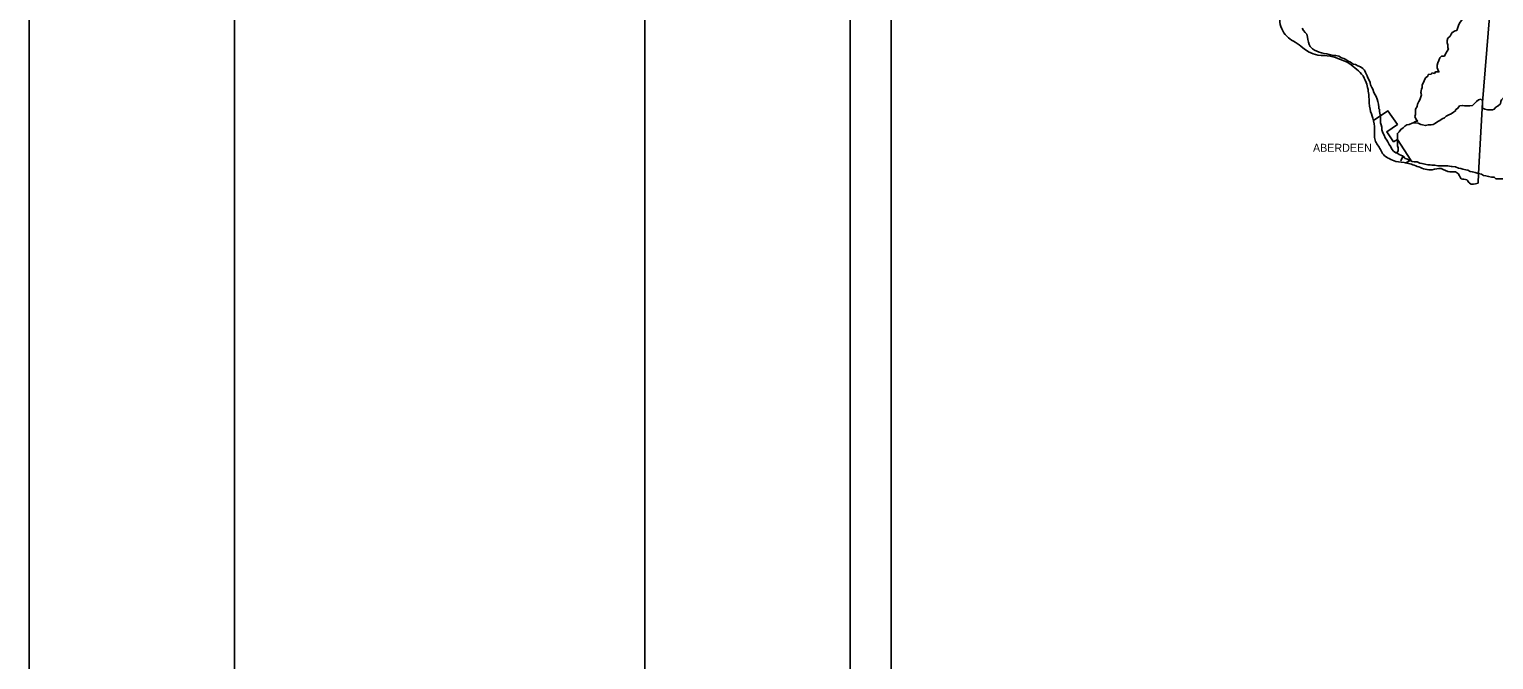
# Model space of a CAD drawing. Extents: x 0 to 34, y 0 to 22.
# Drawn here: x 0 to 3.569, y 14.798 to 16.334 of the extents above; entities that cross this region are included whole.
import ezdxf

# ---------------------------------------------------------------- set-up
doc = ezdxf.new("R2010")
doc.units = 0
for name, color, linetype in [('Default', 7, 'Continuous'), ('SH_Border', 7, 'Continuous'), ('SH_Cut_Line', 7, 'Continuous'), ('SH_Data', 7, 'Continuous')]:
    doc.layers.add(name, color=color, linetype=linetype)

msp = doc.modelspace()

# ---------------------------------------------------------------- linework, layer by layer
at = {"layer": 'Default'}
for points in [[(3.6694, 17.6794), (3.6422, 17.3685), (3.589, 16.7427), (3.5413, 16.1551), (3.5317, 15.9819), (3.5304, 15.9587)], [(3.4649, 16.3214), (3.4676, 16.3255), (3.4745, 16.3296), (3.4786, 16.3309), (3.4813, 16.3378), (3.4826, 16.3432), (3.4854, 16.3487), (3.4895, 16.3541), (3.4922, 16.3582), (3.4963, 16.3637), (3.5004, 16.3691), (3.5031, 16.3746), (3.5031, 16.38), (3.5045, 16.3868), (3.5058, 16.3937), (3.5085, 16.3991), (3.5113, 16.4046), (3.514, 16.41), (3.5167, 16.4155), (3.5195, 16.4209), (3.5167, 16.425), (3.514, 16.4277)], [(3.1022, 16.3364), (3.105, 16.3309), (3.1091, 16.3255), (3.1132, 16.3214), (3.1145, 16.3146), (3.1159, 16.3091), (3.1172, 16.3023), (3.1186, 16.2969), (3.1213, 16.2914), (3.1268, 16.2859), (3.1322, 16.2832), (3.1377, 16.2805), (3.1431, 16.2778), (3.1486, 16.2764), (3.1554, 16.275), (3.1622, 16.2737), (3.1677, 16.2723), (3.1786, 16.2696)], [(3.4186, 16.2273), (3.424, 16.226), (3.4267, 16.23), (3.4349, 16.23), (3.4322, 16.2355), (3.4308, 16.2396), (3.4308, 16.2464), (3.4322, 16.2519), (3.4349, 16.2573), (3.4376, 16.2641), (3.4417, 16.2682), (3.4486, 16.2682), (3.4513, 16.2737), (3.4554, 16.2805), (3.4581, 16.2859), (3.4567, 16.2887), (3.4567, 16.2955), (3.4554, 16.3009), (3.4554, 16.3064), (3.4567, 16.3119), (3.4622, 16.3173), (3.4649, 16.3214), (3.4649, 16.3214)], [(3.1786, 16.2696), (3.1841, 16.2696), (3.1909, 16.2682), (3.1977, 16.2641), (3.2031, 16.2628), (3.2086, 16.26), (3.214, 16.256), (3.2195, 16.2532), (3.2263, 16.2491), (3.2318, 16.2478), (3.2372, 16.245), (3.244, 16.2423), (3.2495, 16.2382), (3.2536, 16.2341), (3.2563, 16.2287), (3.2604, 16.2205), (3.2618, 16.2151), (3.2645, 16.211), (3.2672, 16.2041), (3.2686, 16.1987), (3.2713, 16.1919), (3.274, 16.1878), (3.2768, 16.1796), (3.2795, 16.1741), (3.2822, 16.1701), (3.2849, 16.1632), (3.2863, 16.1578), (3.2877, 16.151), (3.289, 16.1442), (3.289, 16.1401), (3.2904, 16.1387)], [(3.3722, 16.106), (3.3777, 16.1087), (3.3831, 16.1101), (3.379, 16.1155), (3.3763, 16.121), (3.3777, 16.1264), (3.3777, 16.1332), (3.3777, 16.1387), (3.3817, 16.1455), (3.3831, 16.151), (3.3858, 16.1578), (3.3886, 16.1619), (3.3913, 16.1687), (3.3927, 16.1741), (3.3913, 16.1796), (3.3927, 16.1878), (3.394, 16.1919), (3.394, 16.1987), (3.3967, 16.2028), (3.3995, 16.2082), (3.4022, 16.2151), (3.4077, 16.2191), (3.409, 16.2232), (3.4158, 16.2246), (3.4186, 16.2273)], [(3.5413, 16.1551), (3.5413, 16.1469), (3.5413, 16.1414), (3.5467, 16.1387), (3.5535, 16.1373), (3.5604, 16.1373), (3.5658, 16.1373), (3.5699, 16.1387), (3.574, 16.1442), (3.5794, 16.1469), (3.5849, 16.1523), (3.5863, 16.1578), (3.5876, 16.1619), (3.5917, 16.166), (3.5972, 16.1701), (3.6026, 16.1741), (3.6067, 16.1782), (3.6135, 16.1796), (3.619, 16.1837), (3.6244, 16.1864), (3.6299, 16.1837), (3.6367, 16.1823), (3.6394, 16.1837), (3.6394, 16.1837)], [(3.3531, 16.0078), (3.3668, 16.0146), (3.334, 16.0651), (3.3245, 16.0596), (3.3081, 16.0842), (3.334, 16.1019), (3.3109, 16.1346), (3.2754, 16.1114)], [(3.2904, 16.1387), (3.2904, 16.1332), (3.2918, 16.1251), (3.2931, 16.121), (3.2931, 16.1142), (3.2931, 16.106), (3.2945, 16.1005), (3.2959, 16.0951), (3.2959, 16.0883), (3.2986, 16.0814), (3.3013, 16.076), (3.304, 16.0692), (3.3081, 16.0637), (3.3109, 16.0596), (3.3136, 16.0528), (3.3177, 16.0474), (3.3204, 16.0419), (3.3245, 16.0364), (3.3299, 16.0324), (3.3299, 16.0324), (3.3327, 16.0324)], [(3.3722, 16.106), (3.3777, 16.106), (3.3845, 16.1046), (3.3913, 16.1019), (3.3954, 16.1005), (3.4022, 16.0992), (3.409, 16.1005), (3.4158, 16.1005), (3.4213, 16.1019), (3.4267, 16.1046), (3.4322, 16.1087), (3.4376, 16.1114), (3.4431, 16.1155), (3.4486, 16.1182), (3.4526, 16.1223), (3.4595, 16.1251), (3.4649, 16.1278), (3.4704, 16.1319), (3.4758, 16.1346), (3.4758, 16.1373)], [(3.4758, 16.1373), (3.4813, 16.1414), (3.4854, 16.1469), (3.4922, 16.1482), (3.4976, 16.1469), (3.5045, 16.1469), (3.5099, 16.1469), (3.5167, 16.1482), (3.5222, 16.1537), (3.5263, 16.1578), (3.5317, 16.1619), (3.5372, 16.1632), (3.5413, 16.1592), (3.5413, 16.1551), (3.5413, 16.1551)], [(3.3327, 16.0324), (3.3354, 16.0378), (3.3354, 16.0446), (3.334, 16.0501), (3.334, 16.0555), (3.334, 16.061), (3.334, 16.0678), (3.334, 16.0733), (3.334, 16.0801), (3.3381, 16.0842), (3.3422, 16.0896), (3.3477, 16.0937), (3.3518, 16.0978), (3.3572, 16.1005), (3.3627, 16.1019), (3.3695, 16.1046), (3.3722, 16.106)], [(3.3477, 16.0242), (3.3422, 16.0269), (3.3381, 16.0283), (3.3327, 16.0324)], [(3.3327, 16.0324), (3.3381, 16.0283), (3.3422, 16.0269), (3.3477, 16.0242)], [(3.3422, 16.0133), (3.3449, 16.0187), (3.3477, 16.0242)], [(3.3477, 16.0242), (3.3531, 16.0187), (3.3586, 16.0174), (3.3627, 16.0146), (3.3695, 16.0119), (3.3749, 16.0105), (3.3817, 16.0105), (3.3886, 16.0078), (3.394, 16.0064), (3.4008, 16.0051), (3.4077, 16.0037), (3.4131, 16.0037), (3.4186, 16.0024), (3.4254, 16.0024), (3.4322, 16.001), (3.439, 16.001), (3.4445, 16.001), (3.4513, 16.001), (3.4567, 16.001), (3.4649, 15.9996), (3.4676, 15.9996), (3.4758, 15.9983), (3.4826, 15.9955), (3.4881, 15.9942), (3.4935, 15.9928), (3.5004, 15.9915), (3.5058, 15.9901), (3.5113, 15.9874), (3.5167, 15.986), (3.5235, 15.9846), (3.5304, 15.9819), (3.5317, 15.9819), (3.5317, 15.9819)], [(3.5317, 15.9819), (3.5385, 15.9805), (3.544, 15.9778), (3.5494, 15.9765), (3.5563, 15.9751), (3.5631, 15.9737), (3.5699, 15.9737), (3.574, 15.9696), (3.5808, 15.9696), (3.5876, 15.9696), (3.5931, 15.9696), (3.5985, 15.9669), (3.6067, 15.9669), (3.6122, 15.9642), (3.6176, 15.9615), (3.6231, 15.9615), (3.6299, 15.9587), (3.6367, 15.9574), (3.6408, 15.956), (3.6476, 15.9546), (3.6544, 15.9533), (3.6558, 15.9533), (3.6558, 15.9533)]]:
    msp.add_lwpolyline(points, dxfattribs=at)
msp.add_spline([(3.5304, 15.9587), (3.5099, 15.9587), (3.5031, 15.9669), (3.4895, 15.9696), (3.484, 15.9792), (3.4758, 15.986), (3.4622, 15.986), (3.4404, 15.9942), (3.4186, 15.9915), (3.3858, 15.9983), (3.3572, 16.0078), (3.3299, 16.0119), (3.3136, 16.0187), (3.2999, 16.0283), (3.2931, 16.0405), (3.2795, 16.0637), (3.2781, 16.0896), (3.274, 16.1169), (3.2672, 16.1387), (3.2645, 16.1701), (3.2577, 16.2041), (3.2468, 16.2246), (3.2304, 16.2396), (3.2113, 16.2532), (3.195, 16.26), (3.1704, 16.2682), (3.1404, 16.271), (3.1172, 16.2791), (3.1036, 16.2887), (3.0845, 16.3023), (3.0682, 16.3132), (3.0545, 16.3296), (3.0477, 16.3514), (3.0477, 16.3718), (3.0409, 16.3923), (3.0341, 16.4264), (3.0259, 16.4496), (3.0204, 16.4673), (3.0014, 16.485), (2.9795, 16.4986), (2.9495, 16.5164), (2.925, 16.5259), (2.9005, 16.5382), (2.8814, 16.545), (2.8582, 16.5477), (2.8255, 16.5518), (2.7968, 16.5586), (2.7696, 16.5614), (2.7478, 16.5668), (2.7314, 16.5804), (2.7137, 16.6009), (2.6973, 16.6173), (2.6646, 16.6323), (2.6305, 16.6377), (2.5937, 16.6432), (2.5514, 16.6363), (2.5296, 16.6241), (2.5023, 16.6159), (2.4614, 16.6077), (2.4369, 16.6009), (2.4096, 16.5873), (2.3769, 16.5804), (2.3483, 16.575), (2.3278, 16.5682), (2.3074, 16.5723)], degree=3, dxfattribs=at)
at = {"layer": 'SH_Border'}
for points in [[(0.5, 21.5), (1.5, 21.5), (1.5, 0.5), (0.5, 0.5)], [(1.5, 21.5), (33.5, 21.5), (33.5, 0.5), (1.5, 0.5)]]:
    msp.add_lwpolyline(points, close=True, dxfattribs=at)
at = {"layer": 'SH_Cut_Line'}
msp.add_lwpolyline([(0, 0), (34, 0), (34, 22), (0, 22)], close=True, dxfattribs=at)
at = {"layer": 'SH_Data'}
for p, q in [((2, 21), (2, 14)), ((2.1, 20.9), (2.1, 14.1))]:
    msp.add_line(p, q, dxfattribs=at)

# ---------------------------------------------------------------- texts
at = {"layer": 'Default'}
msp.add_text('ABERDEEN', height=0.0195, dxfattribs=at).set_placement((3.1282, 16.0351))

doc.saveas('drawing.dxf')
